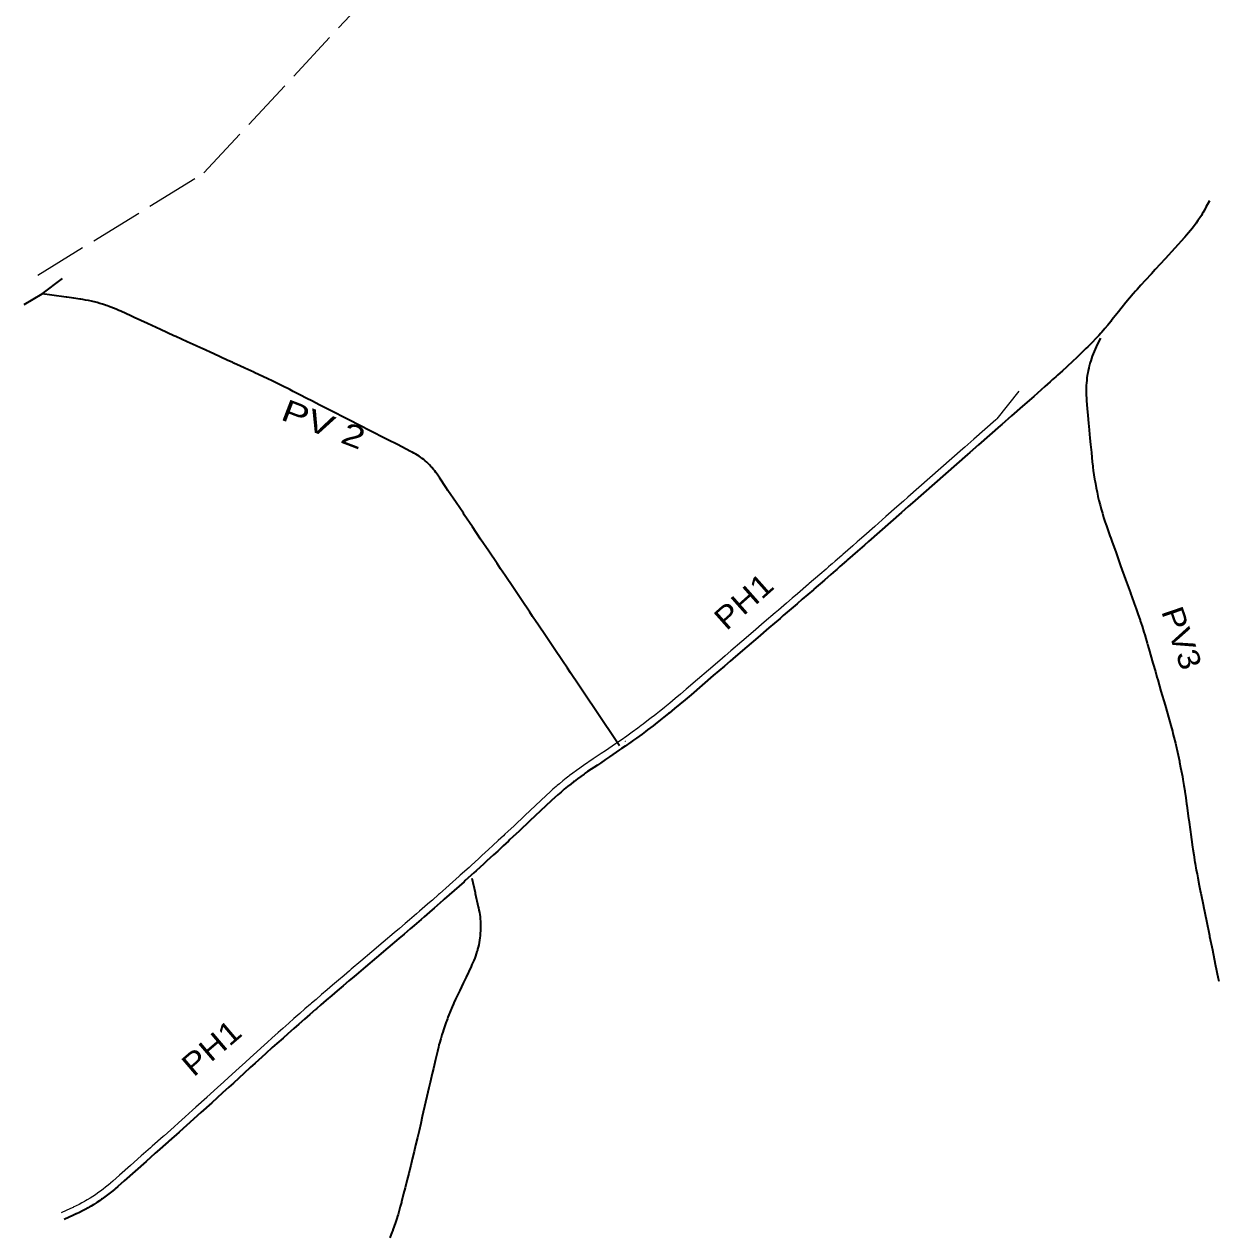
# Model space of a CAD drawing. Extents: x -509392 to -507242, y -1124532 to -1120864.
# Drawn here: x -509392 to -508577, y -1124103 to -1123277 of the extents above; entities that cross this region are included whole.
import ezdxf
from ezdxf.enums import TextEntityAlignment as Align

# ---------------------------------------------------------------- set-up
doc = ezdxf.new("R2010")
doc.units = 0
doc.header["$LTSCALE"] = 6
doc.linetypes.add('DOT_DASHED', pattern=[7.7, 5, -1.2, 0.3, -1.2])
doc.linetypes.add('LONG_DASHED', pattern=[7.5, 6, -1.5])
doc.layers.add('1', color=7, linetype='DOT_DASHED', lineweight=25)
doc.layers.add('15', color=7, linetype='Continuous', lineweight=35)
doc.layers.add('6', color=7, linetype='Continuous')

msp = doc.modelspace()

# ---------------------------------------------------------------- linework, layer by layer
at = {"layer": '1'}
msp.add_line((-509215.666, -1123962.324), (-509215.67, -1123962.327), dxfattribs=at)
at = {"layer": '1', "linetype": 'LONG_DASHED'}
msp.add_lwpolyline([(-509382.968, -1123448.472), (-509269.518, -1123378.636), (-509154.613, -1123254.968), (-509116.796, -1123206.955), (-509083.343, -1123153.123), (-509032.436, -1123148.759), (-509013.527, -1123134.209), (-508975.71, -1123068.738)], dxfattribs=at)
at = {"layer": '1'}
for points in [[(-508713.334, -1123527.623), (-508728.344, -1123546.453), (-508729.125, -1123547.14)], [(-508729.125, -1123547.14), (-508736.634, -1123553.744), (-508744.143, -1123560.348), (-508750.183, -1123565.66), (-508751.652, -1123566.952), (-508759.161, -1123573.556), (-508766.671, -1123580.161), (-508774.18, -1123586.765), (-508781.689, -1123593.369), (-508789.198, -1123599.973), (-508792.168, -1123602.586), (-508796.707, -1123606.577), (-508804.216, -1123613.181), (-508811.725, -1123619.785), (-508819.234, -1123626.39), (-508822.09, -1123628.901), (-508823.737, -1123630.351), (-508826.739, -1123632.986), (-508833.525, -1123638.928), (-508834.257, -1123639.568), (-508838.773, -1123643.509), (-508840.891, -1123645.354), (-508841.786, -1123646.133), (-508843.293, -1123647.445), (-508844.988, -1123648.918), (-508849.329, -1123652.683), (-508856.486, -1123658.875), (-508856.884, -1123659.219), (-508864.453, -1123665.74), (-508868.011, -1123668.796), (-508872.036, -1123672.25), (-508877.493, -1123676.932), (-508879.626, -1123678.763), (-508887.214, -1123685.275), (-508894.803, -1123691.787), (-508902.392, -1123698.299), (-508909.982, -1123704.811), (-508913.752, -1123708.047), (-508917.57, -1123711.324), (-508925.159, -1123717.836), (-508932.747, -1123724.348), (-508940.336, -1123730.86), (-508944.389, -1123734.338), (-508947.901, -1123737.324), (-508947.923, -1123737.342), (-508951.502, -1123740.326), (-508955.1, -1123743.271), (-508955.537, -1123743.624), (-508958.722, -1123746.177), (-508960.985, -1123747.966), (-508962.372, -1123749.051), (-508963.299, -1123749.773), (-508966.048, -1123751.89), (-508969.755, -1123754.698), (-508971.181, -1123755.763), (-508973.481, -1123757.465), (-508977.24, -1123760.202), (-508979.183, -1123761.595), (-508981.019, -1123762.9), (-508984.828, -1123765.566), (-508987.298, -1123767.266), (-508988.66, -1123768.194), (-508995.555, -1123772.876), (-508998.346, -1123774.772), (-509001.809, -1123777.123)], [(-509001.809, -1123777.123), (-509003.828, -1123778.495), (-509010.499, -1123783.025), (-509012.134, -1123784.146), (-509012.915, -1123784.691), (-509015.299, -1123786.386), (-509017.666, -1123788.119), (-509019.999, -1123789.882), (-509020.412, -1123790.197), (-509022.322, -1123791.687), (-509024.609, -1123793.519), (-509026.871, -1123795.383), (-509028.369, -1123796.649), (-509029.111, -1123797.286), (-509031.316, -1123799.211), (-509033.496, -1123801.172), (-509035.643, -1123803.159), (-509035.991, -1123803.486), (-509043.269, -1123810.32), (-509043.291, -1123810.34), (-509050.571, -1123817.176), (-509057.862, -1123824.021), (-509062.061, -1123827.963), (-509064.146, -1123829.918), (-509065.146, -1123830.855), (-509068.661, -1123834.133), (-509072.451, -1123837.649), (-509075.289, -1123840.271), (-509079.789, -1123844.407), (-509081.944, -1123846.38), (-509087.16, -1123851.129), (-509088.627, -1123852.458), (-509094.564, -1123857.812), (-509095.338, -1123858.506), (-509102.011, -1123864.465), (-509102.082, -1123864.53), (-509108.843, -1123870.513), (-509109.471, -1123871.066), (-509113.652, -1123874.736), (-509115.634, -1123876.468), (-509116.976, -1123877.638), (-509122.454, -1123882.395), (-509124.513, -1123884.173), (-509129.3, -1123888.289), (-509132.083, -1123890.67), (-509136.173, -1123894.154), (-509139.69, -1123897.141), (-509147.312, -1123903.614), (-509154.934, -1123910.087), (-509162.556, -1123916.561), (-509168.978, -1123922.015), (-509170.178, -1123923.034), (-509173.836, -1123926.141), (-509177.8, -1123929.508), (-509181.84, -1123932.938), (-509185.427, -1123935.993), (-509189.309, -1123939.314), (-509193.037, -1123942.519), (-509196.042, -1123945.115), (-509196.75, -1123945.728), (-509200.613, -1123949.084), (-509204.157, -1123952.177), (-509208.157, -1123955.686), (-509211.533, -1123958.662), (-509215.666, -1123962.324)], [(-509215.67, -1123962.327), (-509218.878, -1123965.184), (-509223.146, -1123969.003), (-509226.19, -1123971.742), (-509230.589, -1123975.718), (-509233.469, -1123978.334), (-509237.995, -1123982.453), (-509241.236, -1123985.402), (-509245.39, -1123989.184), (-509252.779, -1123995.908), (-509252.807, -1123995.933), (-509255.952, -1123998.796), (-509260.181, -1124002.645), (-509267.556, -1124009.357), (-509267.581, -1124009.38), (-509274.972, -1124016.084), (-509277.239, -1124018.132), (-509282.388, -1124022.766), (-509286.967, -1124026.869), (-509289.827, -1124029.423), (-509296.733, -1124035.565), (-509297.289, -1124036.057), (-509304.773, -1124042.691), (-509306.059, -1124043.831), (-509312.256, -1124049.324), (-509319.739, -1124055.958), (-509327.223, -1124062.591), (-509331.665, -1124066.53), (-509333.308, -1124067.959), (-509333.778, -1124068.357), (-509334.625, -1124069.065), (-509334.955, -1124069.338), (-509336.644, -1124070.699), (-509338.353, -1124072.024), (-509340.086, -1124073.316), (-509341.85, -1124074.581), (-509342.246, -1124074.858), (-509343.622, -1124075.801), (-509345.428, -1124076.994), (-509347.253, -1124078.153), (-509349.103, -1124079.279), (-509350.337, -1124080.004), (-509350.963, -1124080.364), (-509352.856, -1124081.42), (-509354.763, -1124082.438), (-509356.69, -1124083.42), (-509358.64, -1124084.369), (-509358.808, -1124084.448), (-509360.603, -1124085.278), (-509366.979, -1124088.16)]]:
    msp.add_lwpolyline(points, dxfattribs=at)
at = {"layer": '15'}
for points in [[(-508583.402, -1123397.741), (-508585.712, -1123402.086), (-508586.725, -1123403.943), (-508587.776, -1123405.777), (-508588.209, -1123406.508), (-508588.866, -1123407.589), (-508589.993, -1123409.377), (-508591.159, -1123411.141), (-508592.361, -1123412.88), (-508593.6, -1123414.594), (-508593.766, -1123414.817), (-508594.875, -1123416.28), (-508596.185, -1123417.94), (-508597.53, -1123419.571), (-508598.91, -1123421.173), (-508600.125, -1123422.53), (-508600.322, -1123422.746), (-508606.885, -1123429.899), (-508613.645, -1123437.268), (-508620.405, -1123444.636), (-508622.956, -1123447.417), (-508627.166, -1123452.005), (-508630.055, -1123455.154), (-508632.722, -1123458.1), (-508633.886, -1123459.41), (-508635.35, -1123461.082), (-508637.939, -1123464.098), (-508640.378, -1123467.016), (-508640.487, -1123467.148), (-508642.995, -1123470.231), (-508643.882, -1123471.343), (-508645.461, -1123473.348), (-508646.618, -1123474.83), (-508648.782, -1123477.601), (-508650.365, -1123479.602), (-508650.731, -1123480.057), (-508652.718, -1123482.482), (-508652.854, -1123482.646), (-508654.742, -1123484.876), (-508656.804, -1123487.238), (-508657.49, -1123488.006), (-508658.903, -1123489.567), (-508659.45, -1123490.161), (-508661.038, -1123491.863), (-508663.209, -1123494.125), (-508665.415, -1123496.353), (-508666.412, -1123497.338), (-508667.656, -1123498.546), (-508673.608, -1123504.282), (-508673.64, -1123504.312), (-508676.927, -1123507.451), (-508680.243, -1123510.559), (-508680.878, -1123511.148), (-508683.587, -1123513.638), (-508686.959, -1123516.686), (-508688.283, -1123517.868), (-508690.358, -1123519.703), (-508691.967, -1123521.119), (-508692.063, -1123521.203), (-508695.787, -1123524.478), (-508703.296, -1123531.082), (-508710.805, -1123537.686), (-508718.314, -1123544.29), (-508725.042, -1123550.207), (-508725.823, -1123550.895)], [(-509392.163, -1123468.406), (-509380.018, -1123461.185), (-509366.001, -1123450.781)], [(-509199.702, -1123532.229), (-509203.516, -1123530.281), (-509208.594, -1123527.706), (-509209.825, -1123527.087), (-509210.97, -1123526.514), (-509216.158, -1123523.938), (-509217.495, -1123523.28), (-509222.502, -1123520.839), (-509226.454, -1123518.936), (-509228.867, -1123517.785), (-509235.278, -1123514.765), (-509235.447, -1123514.686), (-509241.682, -1123511.803), (-509242.057, -1123511.632), (-509244.498, -1123510.514), (-509249.179, -1123508.37), (-509249.86, -1123508.058), (-509253.59, -1123506.349), (-509262.681, -1123502.184), (-509270.73, -1123498.497), (-509271.773, -1123498.019), (-509274.828, -1123496.619), (-509280.863, -1123493.855), (-509288.717, -1123490.257), (-509289.955, -1123489.69), (-509299.046, -1123485.525), (-509308.138, -1123481.36), (-509317.229, -1123477.195), (-509319.339, -1123476.229), (-509326.322, -1123473.029), (-509327.497, -1123472.491), (-509329.339, -1123471.671), (-509331.173, -1123470.899), (-509333.023, -1123470.167), (-509334.911, -1123469.464), (-509335.148, -1123469.379), (-509336.2, -1123469.01), (-509336.751, -1123468.823), (-509338.658, -1123468.202), (-509340.563, -1123467.628), (-509342.482, -1123467.091), (-509344.261, -1123466.632), (-509344.373, -1123466.604), (-509346.343, -1123466.142), (-509348.29, -1123465.727), (-509350.244, -1123465.354), (-509352.213, -1123465.02), (-509353.578, -1123464.814), (-509354.18, -1123464.73), (-509358.335, -1123464.16), (-509363.092, -1123463.507), (-509363.447, -1123463.458), (-509373.352, -1123462.099), (-509380.018, -1123461.185)], [(-508657.683, -1123491.405), (-508659.904, -1123495.775), (-508660.66, -1123497.308), (-508661.378, -1123498.858), (-508662.046, -1123500.4), (-508662.058, -1123500.426), (-508662.699, -1123502.01), (-508663.302, -1123503.61), (-508663.865, -1123505.223), (-508664.389, -1123506.85), (-508664.745, -1123508.042), (-508664.873, -1123508.489), (-508665.246, -1123509.865), (-508665.317, -1123510.139), (-508665.72, -1123511.8), (-508666.083, -1123513.47), (-508666.404, -1123515.149), (-508666.685, -1123516.834), (-508666.925, -1123518.526), (-508667.065, -1123519.69), (-508667.123, -1123520.224), (-508667.28, -1123521.926), (-508667.395, -1123523.631), (-508667.468, -1123525.338), (-508667.5, -1123527.047), (-508667.49, -1123528.756), (-508667.467, -1123529.673), (-508667.438, -1123530.464), (-508667.344, -1123532.171), (-508667.209, -1123533.874), (-508666.681, -1123539.64), (-508666.297, -1123543.833), (-508665.769, -1123549.599), (-508665.597, -1123551.482), (-508664.857, -1123559.557), (-508664.46, -1123563.895), (-508663.945, -1123569.515), (-508663.639, -1123572.857), (-508663.345, -1123575.823), (-508663.007, -1123578.784), (-508662.923, -1123579.462), (-508662.625, -1123581.74), (-508662.199, -1123584.69), (-508661.729, -1123587.633), (-508661.434, -1123589.35), (-508661.215, -1123590.568), (-508660.657, -1123593.496), (-508660.056, -1123596.415), (-508659.451, -1123599.15), (-508659.412, -1123599.325), (-508658.724, -1123602.225), (-508657.993, -1123605.114), (-508657.219, -1123607.992), (-508656.982, -1123608.84), (-508656.402, -1123610.858), (-508655.543, -1123613.712), (-508654.641, -1123616.553), (-508654.031, -1123618.393), (-508653.697, -1123619.379), (-508652.711, -1123622.192), (-508651.216, -1123626.357), (-508650.691, -1123627.819), (-508649.67, -1123630.663), (-508647.312, -1123637.23), (-508643.933, -1123646.642)], [(-508985.855, -1123769.59), (-508991.433, -1123761.29), (-508997.011, -1123752.99), (-509002.589, -1123744.69), (-509008.166, -1123736.391), (-509013.744, -1123728.091), (-509019.322, -1123719.791), (-509021.5, -1123716.55), (-509024.9, -1123711.491), (-509030.478, -1123703.191), (-509036.056, -1123694.891), (-509041.634, -1123686.591), (-509042.802, -1123684.852), (-509045.191, -1123681.298), (-509047.212, -1123678.292), (-509052.79, -1123669.992), (-509058.367, -1123661.692), (-509063.945, -1123653.392), (-509067.081, -1123648.726), (-509069.523, -1123645.092), (-509075.101, -1123636.793), (-509080.679, -1123628.493), (-509086.257, -1123620.193), (-509091.835, -1123611.893), (-509092.498, -1123610.907), (-509097.413, -1123603.593), (-509102.99, -1123595.293), (-509104.204, -1123593.487), (-509108.568, -1123586.994), (-509109.021, -1123586.32), (-509110.46, -1123584.18), (-509111.245, -1123583.048), (-509112.042, -1123581.969), (-509112.872, -1123580.914), (-509113.746, -1123579.867), (-509114.089, -1123579.474), (-509114.612, -1123578.892), (-509115.543, -1123577.905), (-509116.517, -1123576.93), (-509116.56, -1123576.888), (-509117.464, -1123576.039), (-509118.472, -1123575.146), (-509119.503, -1123574.285), (-509120.578, -1123573.44), (-509120.655, -1123573.382), (-509121.633, -1123572.661), (-509122.738, -1123571.895), (-509123.863, -1123571.164), (-509125.01, -1123570.466), (-509126.177, -1123569.802), (-509127.395, -1123569.157), (-509128.456, -1123568.615), (-509137.389, -1123564.053), (-509137.407, -1123564.043), (-509138.806, -1123563.329), (-509142.705, -1123561.338), (-509146.267, -1123559.519), (-509155.173, -1123554.971), (-509164.079, -1123550.422), (-509169.758, -1123547.522), (-509172.984, -1123545.874), (-509181.89, -1123541.326), (-509190.796, -1123536.777), (-509195.507, -1123534.372), (-509199.703, -1123532.229)], [(-508725.823, -1123550.895), (-508733.332, -1123557.499), (-508740.841, -1123564.103), (-508746.881, -1123569.415), (-508748.35, -1123570.707), (-508755.859, -1123577.311), (-508763.368, -1123583.915), (-508770.877, -1123590.519), (-508778.386, -1123597.124), (-508785.895, -1123603.728), (-508788.866, -1123606.34), (-508793.404, -1123610.332), (-508800.913, -1123616.936), (-508808.422, -1123623.54), (-508815.931, -1123630.144), (-508818.787, -1123632.656), (-508820.437, -1123634.106), (-508823.443, -1123636.745), (-508830.233, -1123642.692), (-508830.967, -1123643.333), (-508835.487, -1123647.278), (-508837.607, -1123649.124), (-508838.504, -1123649.905), (-508840.013, -1123651.218), (-508841.71, -1123652.693), (-508846.054, -1123656.462), (-508853.217, -1123662.659), (-508853.617, -1123663.004), (-508861.193, -1123669.531), (-508864.754, -1123672.59), (-508868.781, -1123676.045), (-508874.236, -1123680.727), (-508876.37, -1123682.557), (-508883.958, -1123689.069), (-508891.547, -1123695.582), (-508899.136, -1123702.094), (-508906.725, -1123708.606), (-508910.496, -1123711.842), (-508914.314, -1123715.118), (-508921.903, -1123721.63), (-508929.492, -1123728.143), (-508937.081, -1123734.655), (-508941.137, -1123738.135), (-508944.684, -1123741.151), (-508944.713, -1123741.175), (-508948.317, -1123744.181), (-508951.949, -1123747.153), (-508952.397, -1123747.515), (-508955.609, -1123750.09), (-508957.896, -1123751.897), (-508959.297, -1123752.994), (-508960.235, -1123753.724), (-508963.012, -1123755.862), (-508966.753, -1123758.696), (-508968.197, -1123759.775), (-508970.521, -1123761.494), (-508974.315, -1123764.257), (-508976.278, -1123765.665), (-508978.134, -1123766.984), (-508981.98, -1123769.675), (-508984.475, -1123771.393), (-508985.85, -1123772.33), (-508992.746, -1123777.013), (-508995.538, -1123778.908), (-508999.001, -1123781.26)], [(-508643.933, -1123646.642), (-508640.555, -1123656.054), (-508637.327, -1123665.046), (-508637.176, -1123665.466), (-508633.797, -1123674.878), (-508633.595, -1123675.441), (-508632.139, -1123679.566), (-508630.729, -1123683.708), (-508630.523, -1123684.326), (-508629.364, -1123687.864), (-508628.044, -1123692.035), (-508627.485, -1123693.854), (-508626.771, -1123696.22), (-508625.777, -1123699.605), (-508625.543, -1123700.419), (-508624.674, -1123703.45), (-508621.92, -1123713.064), (-508620.267, -1123718.832), (-508619.166, -1123722.677), (-508618.615, -1123724.599), (-508616.411, -1123732.29), (-508613.657, -1123741.903), (-508610.903, -1123751.516), (-508610.898, -1123751.531), (-508609.761, -1123755.58), (-508608.667, -1123759.64), (-508608.269, -1123761.163), (-508607.616, -1123763.712), (-508606.607, -1123767.794), (-508605.876, -1123770.872), (-508605.641, -1123771.887), (-508604.718, -1123775.99), (-508603.839, -1123780.102), (-508603.727, -1123780.638), (-508603.003, -1123784.224), (-508602.21, -1123788.353), (-508601.823, -1123790.455), (-508601.46, -1123792.491), (-508600.754, -1123796.637), (-508600.165, -1123800.317), (-508600.092, -1123800.79), (-508599.474, -1123804.949), (-508598.899, -1123809.115), (-508598.753, -1123810.216), (-508597.558, -1123819.226), (-508597.438, -1123820.129), (-508596.375, -1123828.148), (-508596.12, -1123830.042), (-508595.652, -1123833.418), (-508594.882, -1123838.682), (-508594.692, -1123839.939), (-508594.066, -1123843.939), (-508593.204, -1123849.189), (-508593.098, -1123849.811), (-508592.294, -1123854.431), (-508591.836, -1123856.975), (-508591.34, -1123859.656), (-508591.339, -1123859.664), (-508590.337, -1123864.889), (-508589.419, -1123869.469), (-508589.288, -1123870.105), (-508587.476, -1123878.92), (-508587.405, -1123879.264), (-508585.391, -1123889.059), (-508583.377, -1123898.854)], [(-508999.001, -1123781.26), (-509001.019, -1123782.631), (-509007.687, -1123787.159), (-509009.286, -1123788.256), (-509010.042, -1123788.783), (-509012.374, -1123790.441), (-509014.682, -1123792.131), (-509016.965, -1123793.855), (-509017.358, -1123794.157), (-509019.223, -1123795.611), (-509021.456, -1123797.399), (-509023.664, -1123799.219), (-509025.125, -1123800.454), (-509025.845, -1123801.071), (-509027.999, -1123802.953), (-509030.126, -1123804.866), (-509032.226, -1123806.809), (-509032.568, -1123807.131), (-509039.859, -1123813.976), (-509039.88, -1123813.996), (-509047.149, -1123820.821), (-509054.439, -1123827.666), (-509058.639, -1123831.61), (-509060.729, -1123833.568), (-509061.732, -1123834.507), (-509065.256, -1123837.794), (-509069.054, -1123841.319), (-509071.9, -1123843.948), (-509076.41, -1123848.093), (-509078.573, -1123850.072), (-509083.799, -1123854.831), (-509085.273, -1123856.166), (-509091.223, -1123861.531), (-509092, -1123862.229), (-509098.679, -1123868.194), (-509098.755, -1123868.262), (-509105.537, -1123874.264), (-509106.169, -1123874.82), (-509110.358, -1123878.497), (-509112.346, -1123880.235), (-509113.692, -1123881.409), (-509119.182, -1123886.176), (-509121.247, -1123887.959), (-509126.045, -1123892.085), (-509128.836, -1123894.472), (-509132.935, -1123897.964), (-509136.453, -1123900.951), (-509144.075, -1123907.425), (-509151.697, -1123913.898), (-509159.319, -1123920.371), (-509165.741, -1123925.826), (-509166.941, -1123926.845), (-509170.599, -1123929.951), (-509174.563, -1123933.318), (-509178.602, -1123936.748), (-509182.182, -1123939.796), (-509186.054, -1123943.109), (-509189.772, -1123946.306), (-509192.77, -1123948.896), (-509193.475, -1123949.506), (-509197.33, -1123952.854), (-509200.865, -1123955.939), (-509204.855, -1123959.44), (-509208.223, -1123962.409), (-509212.347, -1123966.063)], [(-509086.647, -1123859.773), (-509084.486, -1123869.536), (-509084.324, -1123870.27), (-509082.326, -1123879.3), (-509082.163, -1123880.033), (-509081.84, -1123881.591), (-509081.559, -1123883.156), (-509081.319, -1123884.729), (-509081.12, -1123886.307), (-509080.964, -1123887.89), (-509080.868, -1123889.182), (-509080.85, -1123889.477), (-509080.777, -1123891.066), (-509080.747, -1123892.656), (-509080.759, -1123894.247), (-509080.789, -1123895.254), (-509080.814, -1123895.837), (-509080.91, -1123897.424), (-509081.048, -1123899.009), (-509081.065, -1123899.168), (-509081.229, -1123900.589), (-509081.451, -1123902.164), (-509081.715, -1123903.733), (-509082.02, -1123905.294), (-509082.367, -1123906.847), (-509082.754, -1123908.389), (-509082.915, -1123908.984), (-509083.183, -1123909.921), (-509083.652, -1123911.441), (-509084.161, -1123912.948), (-509084.709, -1123914.441), (-509085.298, -1123915.919), (-509085.925, -1123917.381), (-509086.369, -1123918.356), (-509086.59, -1123918.826), (-509087.196, -1123920.095), (-509090.672, -1123927.383), (-509090.895, -1123927.852), (-509092.655, -1123931.541), (-509094.977, -1123936.409), (-509096.529, -1123939.664), (-509097.764, -1123942.302), (-509098.96, -1123944.959), (-509099.189, -1123945.478), (-509100.118, -1123947.632), (-509101.236, -1123950.322), (-509102.315, -1123953.027), (-509102.972, -1123954.734), (-509103.355, -1123955.749), (-509104.355, -1123958.485), (-509105.315, -1123961.235), (-509106.234, -1123963.999), (-509106.289, -1123964.167), (-509107.114, -1123966.776), (-509107.953, -1123969.566), (-509108.751, -1123972.367), (-509109.105, -1123973.662), (-509109.129, -1123973.754), (-509109.508, -1123975.18), (-509110.224, -1123978.004), (-509110.899, -1123980.838), (-509111.505, -1123983.467), (-509112.921, -1123989.608), (-509113.751, -1123993.211), (-509115.12, -1123999.151)], [(-508583.377, -1123898.854), (-508583.231, -1123899.566), (-508581.363, -1123908.65), (-508579.349, -1123918.445), (-508577.335, -1123928.24), (-508576.966, -1123930.034)], [(-509212.347, -1123966.063), (-509215.549, -1123968.914), (-509219.806, -1123972.724), (-509222.843, -1123975.456), (-509227.231, -1123979.422), (-509230.105, -1123982.033), (-509234.629, -1123986.15), (-509237.87, -1123989.1), (-509242.025, -1123992.881), (-509249.421, -1123999.612), (-509249.449, -1123999.638), (-509252.587, -1124002.494), (-509256.816, -1124006.343), (-509264.186, -1124013.05), (-509264.212, -1124013.074), (-509271.619, -1124019.792), (-509273.891, -1124021.844), (-509279.048, -1124026.486), (-509283.634, -1124030.596), (-509286.499, -1124033.155), (-509293.416, -1124039.305), (-509293.973, -1124039.799), (-509301.456, -1124046.433), (-509302.742, -1124047.573), (-509308.939, -1124053.066), (-509316.422, -1124059.7), (-509323.905, -1124066.333), (-509328.355, -1124070.277), (-509330.057, -1124071.758), (-509330.554, -1124072.18), (-509331.433, -1124072.915), (-509331.787, -1124073.206), (-509333.544, -1124074.622), (-509335.327, -1124076.004), (-509337.135, -1124077.353), (-509338.969, -1124078.667), (-509339.393, -1124078.964), (-509340.827, -1124079.947), (-509342.709, -1124081.191), (-509344.614, -1124082.4), (-509346.541, -1124083.573), (-509347.828, -1124084.329), (-509348.49, -1124084.709), (-509350.46, -1124085.809), (-509352.45, -1124086.871), (-509354.46, -1124087.896), (-509356.489, -1124088.883), (-509356.681, -1124088.973), (-509358.536, -1124089.831), (-509364.92, -1124092.716)], [(-509115.12, -1123999.151), (-509115.997, -1124002.956), (-509117.339, -1124008.775), (-509118.244, -1124012.7), (-509120.49, -1124022.444), (-509121.592, -1124027.227), (-509122.742, -1124032.188), (-509123.204, -1124034.162), (-509123.824, -1124036.801), (-509125.038, -1124041.921), (-509126.102, -1124046.363), (-509127.381, -1124051.642), (-509128.428, -1124055.915), (-509128.616, -1124056.68), (-509129.774, -1124061.351), (-509130.8, -1124065.454), (-509132.215, -1124071.049), (-509133.22, -1124074.982), (-509134.696, -1124080.736), (-509134.774, -1124081.042), (-509135.5, -1124083.79), (-509136.265, -1124086.527), (-509137.069, -1124089.253), (-509137.407, -1124090.361), (-509137.911, -1124091.968), (-509138.791, -1124094.67), (-509139.711, -1124097.359), (-509140.596, -1124099.838), (-509140.668, -1124100.035), (-509141.663, -1124102.697), (-509142.696, -1124105.345)]]:
    msp.add_lwpolyline(points, dxfattribs=at)

# ---------------------------------------------------------------- texts
at = {"layer": '1'}
for s, rotation, width, p in [('PV 2', 339.042, 1.35, (-509190.553, -1123557.17)), ('PH1', 41.505, 1.15, (-508896.211, -1123676.579)), ('PV3', 288.848, 1.15, (-508609.37, -1123698.397)), ('PH1', 40.542, 1.15, (-509259.505, -1123981.357))]:
    msp.add_text(s, height=15, rotation=rotation, dxfattribs=dict(at, width=width)).set_placement(p, align=Align.CENTER)
at = {"layer": '6', "width": 1.5}
msp.add_text('A', height=1, rotation=123.903, dxfattribs=at).set_placement((-508981.478, -1123766.243), align=Align.CENTER)
msp.add_text('A', height=1, rotation=123.903, dxfattribs=at).set_placement((-508981.478, -1123766.243), align=Align.CENTER)

doc.saveas('drawing.dxf')
